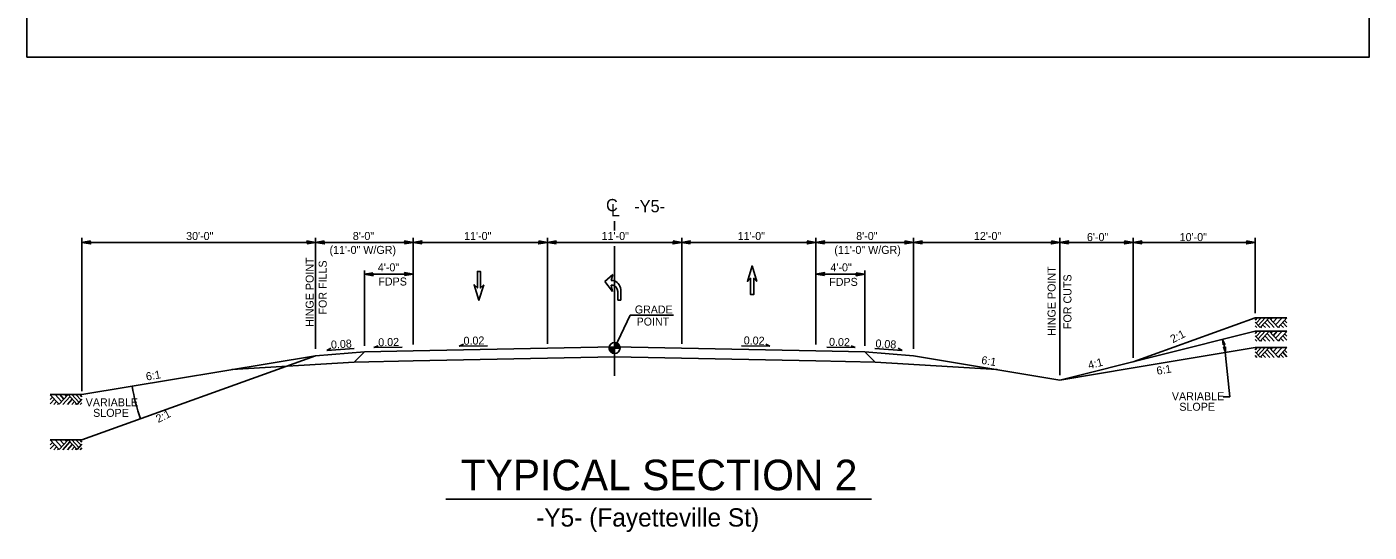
# Model space of a CAD drawing. Extents: x 1901718 to 1902220, y 193828 to 194187.
# Drawn here: x 1901718.5 to 1901828.5, y 194063.4 to 194104.8 of the extents above; entities that cross this region are included whole.
import ezdxf

# ---------------------------------------------------------------- set-up
doc = ezdxf.new("R2010")
doc.units = 0
for name, color, linetype in [('Default', 7, 'Continuous'), ('MARK BIKE LEFT ARROW CELL', 7, 'Continuous'), ('Old_Level_1', 7, 'Continuous'), ('Old_Level_2', 7, 'Continuous'), ('Prop Dimension', 7, 'Continuous'), ('Prop Dimension Text', 7, 'Continuous'), ('Scratch_Level_0', 7, 'Continuous'), ('Typical Hinge Slope Interstate CELL', 7, 'Continuous'), ('Typical Pavement Slope CELL', 7, 'Continuous'), ('Typical Terminator CELL', 7, 'Continuous'), ('Typical Text Grade Point CELL', 7, 'Continuous')]:
    doc.layers.add(name, color=color, linetype=linetype)

# ---------------------------------------------------------------- blocks, each defined once
blk = doc.blocks.new('TERMINATOR')
at = {"layer": 'Typical Terminator CELL'}
blk.add_lwpolyline([(-0.469, 0.081), (0, 0), (-0.471, -0.083), (-0.411, 0)], close=True, dxfattribs=at)

msp = doc.modelspace()

# ---------------------------------------------------------------- linework, layer by layer
at = {"layer": 'Default'}
msp.add_arc((1901742.14, 194077.84), 15.24, 189.4623, 199.8119, dxfattribs=at)
at = {"layer": 'MARK BIKE LEFT ARROW CELL'}
for p, q in [((1901766.5, 194084.5), (1901765.85, 194083.92)), ((1901766.5, 194084.5), (1901765.85, 194083.92)), ((1901766.35, 194083.99), (1901766.5, 194084.5)), ((1901766.35, 194083.99), (1901766.5, 194084.5)), ((1901765.85, 194083.92), (1901766.47, 194083.11)), ((1901765.85, 194083.92), (1901766.47, 194083.11)), ((1901766.52, 194083.99), (1901766.35, 194083.99)), ((1901766.52, 194083.99), (1901766.35, 194083.99)), ((1901766.47, 194083.11), (1901766.35, 194083.63)), ((1901766.35, 194083.63), (1901766.5, 194083.63)), ((1901766.47, 194083.11), (1901766.35, 194083.63)), ((1901766.35, 194083.63), (1901766.5, 194083.63)), ((1901766.92, 194083.11), (1901766.92, 194082.4)), ((1901766.92, 194083.11), (1901766.92, 194082.4)), ((1901767.15, 194082.4), (1901767.15, 194083.26)), ((1901767.15, 194082.4), (1901767.15, 194083.26)), ((1901766.92, 194082.4), (1901767.15, 194082.4)), ((1901766.92, 194082.4), (1901767.15, 194082.4))]:
    msp.add_line(p, q, dxfattribs=at)
for centre, major_axis, ratio in [((1901766.57, 194083.17), (-0.204, 0.44), 0.652763), ((1901766.57, 194083.17), (-0.204, 0.44), 0.652763), ((1901766.59, 194083.33), (-0.294, 0.632), 0.75825), ((1901766.59, 194083.33), (-0.294, 0.632), 0.75825)]:
    msp.add_ellipse(centre, major_axis=major_axis, ratio=ratio, start_param=4.277405, end_param=5.848201, dxfattribs=at)
at = {"layer": 'Old_Level_1'}
for p, q in [((1901766.64, 194088.1), (1901766.64, 194088.85)), ((1901766.64, 194076.18), (1901766.64, 194086.82)), ((1901819.31, 194080.94), (1901819.14, 194080.76)), ((1901819.63, 194080.94), (1901819.21, 194080.5)), ((1901819.96, 194080.94), (1901819.38, 194080.32)), ((1901820.28, 194080.94), (1901819.54, 194080.15)), ((1901820.7, 194080.14), (1901820.12, 194080.77)), ((1901821.01, 194080.16), (1901820.28, 194080.94)), ((1901820.55, 194080.94), (1901820.41, 194080.8)), ((1901820.95, 194080.94), (1901820.61, 194080.58)), ((1901821.35, 194080.94), (1901820.81, 194080.37)), ((1901821.74, 194080.93), (1901821.01, 194080.16)), ((1901821.74, 194080.53), (1901821.55, 194080.73)), ((1901819.54, 194080.15), (1901819.14, 194080.58)), ((1901819.27, 194080.14), (1901819.14, 194080.28)), ((1901819.31, 194079.84), (1901819.14, 194079.66)), ((1901819.63, 194079.84), (1901819.21, 194079.4)), ((1901819.96, 194079.84), (1901819.38, 194079.22)), ((1901820.28, 194079.84), (1901819.54, 194079.04)), ((1901819.67, 194080.14), (1901819.6, 194080.21)), ((1901819.97, 194080.14), (1901819.75, 194080.37)), ((1901820.33, 194080.14), (1901819.93, 194080.57)), ((1901820.7, 194079.04), (1901820.12, 194079.66)), ((1901821.01, 194079.05), (1901820.28, 194079.84)), ((1901820.55, 194079.84), (1901820.41, 194079.7)), ((1901820.95, 194079.84), (1901820.61, 194079.48)), ((1901821.35, 194079.84), (1901820.81, 194079.27)), ((1901821.74, 194079.83), (1901821.01, 194079.05)), ((1901821.14, 194080.14), (1901821.07, 194080.21)), ((1901821.45, 194080.14), (1901821.22, 194080.38)), ((1901821.74, 194080.2), (1901821.39, 194080.57)), ((1901821.74, 194079.43), (1901821.55, 194079.63)), ((1901746.92, 194078.5), (1901747.26, 194078.66)), ((1901749.24, 194078.54), (1901746.92, 194078.5)), ((1901766.64, 194078.58), (1901750.14, 194078.25)), ((1901753.91, 194078.62), (1901754.25, 194078.78)), ((1901756.23, 194078.66), (1901753.91, 194078.62)), ((1901766.64, 194078.47), (1901766.64, 194078.92)), ((1901766.64, 194078.58), (1901783.14, 194078.25)), ((1901777.04, 194078.66), (1901779.36, 194078.62)), ((1901779.36, 194078.62), (1901779.03, 194078.78)), ((1901784.04, 194078.54), (1901786.35, 194078.5)), ((1901786.35, 194078.5), (1901786.02, 194078.66)), ((1901817.05, 194074.47), (1901816.61, 194078.64)), ((1901819.54, 194079.04), (1901819.14, 194079.48)), ((1901819.27, 194079.04), (1901819.14, 194079.18)), ((1901819.31, 194078.51), (1901819.14, 194078.32)), ((1901819.63, 194078.51), (1901819.21, 194078.06)), ((1901819.96, 194078.51), (1901819.38, 194077.88)), ((1901820.28, 194078.51), (1901819.54, 194077.71)), ((1901819.67, 194079.04), (1901819.6, 194079.11)), ((1901819.97, 194079.04), (1901819.75, 194079.27)), ((1901820.33, 194079.04), (1901819.93, 194079.46)), ((1901821.01, 194077.72), (1901820.28, 194078.51)), ((1901820.55, 194078.51), (1901820.41, 194078.36)), ((1901820.95, 194078.51), (1901820.61, 194078.15)), ((1901821.35, 194078.51), (1901820.81, 194077.93)), ((1901821.14, 194079.04), (1901821.07, 194079.11)), ((1901821.45, 194079.04), (1901821.22, 194079.28)), ((1901821.74, 194079.1), (1901821.39, 194079.46)), ((1901746.14, 194078.17), (1901742.14, 194077.84)), ((1901743.07, 194078.27), (1901743.4, 194078.45)), ((1901745.31, 194078.42), (1901743.07, 194078.27)), ((1901745.29, 194077.32), (1901746.14, 194078.17)), ((1901750.14, 194077.42), (1901745.29, 194077.32)), ((1901750.14, 194078.25), (1901746.14, 194078.17)), ((1901766.64, 194077.75), (1901750.14, 194077.42)), ((1901766.19, 194078.47), (1901766.64, 194078.47)), ((1901767.09, 194078.47), (1901766.64, 194078.47)), ((1901766.64, 194078.02), (1901766.64, 194078.47)), ((1901766.64, 194078.47), (1901766.64, 194078.02)), ((1901766.64, 194077.75), (1901783.14, 194077.42)), ((1901783.14, 194078.25), (1901787.14, 194078.17)), ((1901783.14, 194077.42), (1901787.99, 194077.32)), ((1901787.99, 194077.32), (1901787.14, 194078.17)), ((1901787.14, 194078.17), (1901791.14, 194077.84)), ((1901787.97, 194078.42), (1901790.2, 194078.27)), ((1901790.2, 194078.27), (1901789.88, 194078.45)), ((1901791.14, 194077.84), (1901803.14, 194075.84)), ((1901819.54, 194077.71), (1901819.14, 194078.15)), ((1901819.27, 194077.7), (1901819.14, 194077.85)), ((1901819.67, 194077.7), (1901819.6, 194077.78)), ((1901819.97, 194077.7), (1901819.75, 194077.94)), ((1901820.33, 194077.7), (1901819.93, 194078.13)), ((1901820.7, 194077.7), (1901820.12, 194078.33)), ((1901821.74, 194078.5), (1901821.01, 194077.72)), ((1901821.14, 194077.7), (1901821.07, 194077.78)), ((1901821.45, 194077.7), (1901821.22, 194077.95)), ((1901821.74, 194077.76), (1901821.39, 194078.13)), ((1901821.74, 194078.1), (1901821.55, 194078.3)), ((1901745.29, 194077.32), (1901735.28, 194076.7)), ((1901787.99, 194077.32), (1901797.99, 194076.7)), ((1901720.39, 194074.64), (1901721.12, 194073.86)), ((1901720.39, 194074.24), (1901720.58, 194074.44)), ((1901720.39, 194073.91), (1901720.74, 194074.27)), ((1901720.79, 194074.65), (1901721.32, 194074.08)), ((1901721.12, 194073.86), (1901721.85, 194074.65)), ((1901721.18, 194074.65), (1901721.52, 194074.29)), ((1901721.43, 194073.84), (1901722.01, 194074.47)), ((1901721.59, 194074.65), (1901721.72, 194074.51)), ((1901721.8, 194073.84), (1901722.2, 194074.27)), ((1901721.85, 194074.65), (1901722.59, 194073.85)), ((1901722.17, 194074.65), (1901722.75, 194074.03)), ((1901722.5, 194074.65), (1901722.92, 194074.21)), ((1901722.59, 194073.85), (1901722.99, 194074.29)), ((1901722.82, 194074.65), (1901722.99, 194074.47)), ((1901817.05, 194074.47), (1901816.5, 194074.47)), ((1901720.68, 194073.84), (1901720.91, 194074.09)), ((1901720.99, 194073.84), (1901721.06, 194073.92)), ((1901722.16, 194073.84), (1901722.38, 194074.08)), ((1901722.46, 194073.84), (1901722.53, 194073.92)), ((1901722.86, 194073.84), (1901722.99, 194073.99)), ((1901720.39, 194070.94), (1901721.12, 194070.16)), ((1901720.79, 194070.94), (1901721.32, 194070.37)), ((1901721.12, 194070.16), (1901721.85, 194070.94)), ((1901721.18, 194070.94), (1901721.52, 194070.59)), ((1901721.59, 194070.94), (1901721.72, 194070.8)), ((1901721.85, 194070.94), (1901722.59, 194070.15)), ((1901722.17, 194070.94), (1901722.75, 194070.32)), ((1901722.5, 194070.94), (1901722.92, 194070.5)), ((1901722.82, 194070.94), (1901722.99, 194070.76)), ((1901720.39, 194070.54), (1901720.58, 194070.74)), ((1901720.39, 194070.2), (1901720.74, 194070.57)), ((1901720.68, 194070.14), (1901720.91, 194070.38)), ((1901720.99, 194070.14), (1901721.06, 194070.22)), ((1901721.43, 194070.14), (1901722.01, 194070.77)), ((1901721.8, 194070.14), (1901722.2, 194070.57)), ((1901722.16, 194070.14), (1901722.38, 194070.37)), ((1901722.46, 194070.14), (1901722.53, 194070.21)), ((1901722.59, 194070.15), (1901722.99, 194070.58)), ((1901722.86, 194070.14), (1901722.99, 194070.28)), ((1901752.81, 194066.09), (1901787.7, 194066.09))]:
    msp.add_line(p, q, dxfattribs=at)
for points in [[(1901821.74, 194080.94), (1901819.14, 194080.94)], [(1901821.74, 194079.84), (1901819.14, 194079.84)], [(1901766.64, 194078.92), (1901766.64, 194078.92), (1901766.64, 194078.47)], [(1901766.65, 194078.92), (1901766.65, 194078.47)], [(1901766.66, 194078.92), (1901766.66, 194078.47)], [(1901766.67, 194078.92), (1901766.67, 194078.47)], [(1901766.68, 194078.92), (1901766.68, 194078.47)], [(1901766.69, 194078.92), (1901766.69, 194078.47)], [(1901766.69, 194078.92), (1901766.69, 194078.47)], [(1901766.7, 194078.92), (1901766.7, 194078.47)], [(1901766.71, 194078.92), (1901766.71, 194078.47)], [(1901766.72, 194078.92), (1901766.72, 194078.47)], [(1901766.73, 194078.91), (1901766.73, 194078.47)], [(1901766.74, 194078.91), (1901766.74, 194078.47)], [(1901766.75, 194078.91), (1901766.75, 194078.47)], [(1901766.76, 194078.91), (1901766.76, 194078.47)], [(1901766.77, 194078.9), (1901766.77, 194078.47)], [(1901766.78, 194078.9), (1901766.78, 194078.47)], [(1901766.78, 194078.9), (1901766.78, 194078.47)], [(1901766.79, 194078.9), (1901766.79, 194078.47)], [(1901766.8, 194078.89), (1901766.8, 194078.47)], [(1901766.81, 194078.89), (1901766.81, 194078.47)], [(1901766.82, 194078.88), (1901766.82, 194078.47)], [(1901766.83, 194078.88), (1901766.83, 194078.47)], [(1901766.84, 194078.88), (1901766.84, 194078.47)], [(1901766.85, 194078.87), (1901766.85, 194078.47)], [(1901766.86, 194078.87), (1901766.86, 194078.47)], [(1901766.87, 194078.86), (1901766.87, 194078.47)], [(1901766.87, 194078.86), (1901766.87, 194078.47)], [(1901766.88, 194078.85), (1901766.88, 194078.47)], [(1901766.89, 194078.84), (1901766.89, 194078.47)], [(1901766.9, 194078.84), (1901766.9, 194078.47)], [(1901766.91, 194078.83), (1901766.91, 194078.47)], [(1901766.92, 194078.82), (1901766.92, 194078.47)], [(1901766.93, 194078.82), (1901766.93, 194078.47)], [(1901766.94, 194078.81), (1901766.94, 194078.47)], [(1901766.95, 194078.8), (1901766.95, 194078.47)], [(1901766.96, 194078.79), (1901766.96, 194078.47)], [(1901766.96, 194078.78), (1901766.96, 194078.47)], [(1901766.97, 194078.77), (1901766.97, 194078.47)], [(1901766.98, 194078.76), (1901766.98, 194078.47)], [(1901766.99, 194078.75), (1901766.99, 194078.47)], [(1901767, 194078.74), (1901767, 194078.47)], [(1901767.01, 194078.72), (1901767.01, 194078.47)], [(1901767.02, 194078.71), (1901767.02, 194078.47)], [(1901767.03, 194078.7), (1901767.03, 194078.47)], [(1901767.04, 194078.68), (1901767.04, 194078.47)], [(1901767.05, 194078.66), (1901767.05, 194078.47)], [(1901767.05, 194078.64), (1901767.05, 194078.47)], [(1901767.06, 194078.61), (1901767.06, 194078.47)], [(1901767.07, 194078.58), (1901767.07, 194078.47)], [(1901767.08, 194078.54), (1901767.08, 194078.47)], [(1901821.74, 194078.51), (1901819.14, 194078.51)], [(1901766.19, 194078.47), (1901766.19, 194078.42)], [(1901766.2, 194078.47), (1901766.2, 194078.37)], [(1901766.21, 194078.47), (1901766.21, 194078.34)], [(1901766.22, 194078.47), (1901766.22, 194078.31)], [(1901766.22, 194078.47), (1901766.22, 194078.29)], [(1901766.23, 194078.47), (1901766.23, 194078.27)], [(1901766.24, 194078.47), (1901766.24, 194078.26)], [(1901766.25, 194078.47), (1901766.25, 194078.24)], [(1901766.26, 194078.47), (1901766.26, 194078.23)], [(1901766.27, 194078.47), (1901766.27, 194078.21)], [(1901766.28, 194078.47), (1901766.28, 194078.2)], [(1901766.29, 194078.47), (1901766.29, 194078.19)], [(1901766.3, 194078.47), (1901766.3, 194078.18)], [(1901766.31, 194078.47), (1901766.31, 194078.17)], [(1901766.31, 194078.47), (1901766.31, 194078.16)], [(1901766.32, 194078.47), (1901766.32, 194078.15)], [(1901766.33, 194078.47), (1901766.33, 194078.14)], [(1901766.34, 194078.47), (1901766.34, 194078.13)], [(1901766.35, 194078.47), (1901766.35, 194078.13)], [(1901766.36, 194078.47), (1901766.36, 194078.12)], [(1901766.37, 194078.47), (1901766.37, 194078.11)], [(1901766.38, 194078.47), (1901766.38, 194078.11)], [(1901766.39, 194078.47), (1901766.39, 194078.1)], [(1901766.4, 194078.47), (1901766.4, 194078.09)], [(1901766.4, 194078.47), (1901766.4, 194078.09)], [(1901766.41, 194078.47), (1901766.41, 194078.08)], [(1901766.42, 194078.47), (1901766.42, 194078.08)], [(1901766.43, 194078.47), (1901766.43, 194078.07)], [(1901766.44, 194078.47), (1901766.44, 194078.07)], [(1901766.45, 194078.47), (1901766.45, 194078.06)], [(1901766.46, 194078.47), (1901766.46, 194078.06)], [(1901766.47, 194078.47), (1901766.47, 194078.06)], [(1901766.48, 194078.47), (1901766.48, 194078.05)], [(1901766.49, 194078.47), (1901766.49, 194078.05)], [(1901766.49, 194078.47), (1901766.49, 194078.05)], [(1901766.5, 194078.47), (1901766.5, 194078.04)], [(1901766.51, 194078.47), (1901766.51, 194078.04)], [(1901766.52, 194078.47), (1901766.52, 194078.04)], [(1901766.53, 194078.47), (1901766.53, 194078.04)], [(1901766.54, 194078.47), (1901766.54, 194078.03)], [(1901766.55, 194078.47), (1901766.55, 194078.03)], [(1901766.56, 194078.47), (1901766.56, 194078.03)], [(1901766.57, 194078.47), (1901766.57, 194078.03)], [(1901766.58, 194078.47), (1901766.58, 194078.03)], [(1901766.58, 194078.47), (1901766.58, 194078.03)], [(1901766.59, 194078.47), (1901766.59, 194078.03)], [(1901766.6, 194078.47), (1901766.6, 194078.02)], [(1901766.61, 194078.47), (1901766.61, 194078.02)], [(1901766.62, 194078.47), (1901766.62, 194078.02)], [(1901766.63, 194078.47), (1901766.63, 194078.02), (1901766.63, 194078.02)], [(1901720.39, 194074.65), (1901722.99, 194074.65)], [(1901720.39, 194070.94), (1901722.99, 194070.94)]]:
    msp.add_lwpolyline(points, dxfattribs=at)
for points in [[(1901816.51, 194078.72), (1901816.47, 194079.17), (1901816.66, 194078.76), (1901816.57, 194078.79)], [(1901816.7, 194078.56), (1901816.71, 194078.1), (1901816.55, 194078.53), (1901816.64, 194078.49)]]:
    msp.add_lwpolyline(points, close=True, dxfattribs=at)
msp.add_circle((1901766.64, 194078.47), 0.45, dxfattribs=at)
for centre, radius, start, end in [((1901766.64, 194078.47), 0.45, 359.9905, 89.9905), ((1901807.64, 194076.59), 9.2, 9.4623, 16.3025), ((1901766.64, 194078.47), 0.45, 179.9905, 269.9905)]:
    msp.add_arc(centre, radius, start, end, dxfattribs=at)
at = {"layer": 'Prop Dimension'}
for p, q in [((1901722.99, 194074.94), (1901722.99, 194087.49)), ((1901750.14, 194079.8), (1901750.14, 194087.49)), ((1901761.14, 194078.81), (1901761.14, 194087.49)), ((1901772.14, 194078.81), (1901772.14, 194087.49)), ((1901783.14, 194079.8), (1901783.14, 194087.49)), ((1901750.14, 194087.12), (1901761.14, 194087.12)), ((1901761.14, 194087.12), (1901772.14, 194087.12)), ((1901772.14, 194087.12), (1901783.14, 194087.12))]:
    msp.add_line(p, q, dxfattribs=at)
for points in [[(1901778.31, 194083.93), (1901778.04, 194084.18), (1901778.04, 194082.85), (1901777.79, 194082.85), (1901777.79, 194084.18), (1901777.52, 194083.93), (1901777.91, 194085.2)], [(1901778.31, 194083.93), (1901778.04, 194084.18), (1901778.04, 194082.85), (1901777.79, 194082.85), (1901777.79, 194084.18), (1901777.52, 194083.93), (1901777.91, 194085.2)], [(1901755.92, 194083.65), (1901755.65, 194083.4), (1901755.65, 194084.74), (1901755.4, 194084.74), (1901755.4, 194083.4), (1901755.13, 194083.65), (1901755.53, 194082.38)], [(1901755.92, 194083.65), (1901755.65, 194083.4), (1901755.65, 194084.74), (1901755.4, 194084.74), (1901755.4, 194083.4), (1901755.13, 194083.65), (1901755.53, 194082.38)]]:
    msp.add_lwpolyline(points, close=True, dxfattribs=at)
at = {"layer": 'Prop Dimension Text'}
for p, q in [((1901742.14, 194078.64), (1901742.14, 194087.49)), ((1901742.14, 194078.4), (1901742.14, 194087.49)), ((1901750.14, 194078.75), (1901750.14, 194087.49)), ((1901783.14, 194078.75), (1901783.14, 194087.49)), ((1901791.14, 194078.4), (1901791.14, 194087.49)), ((1901803.14, 194076.25), (1901803.14, 194087.49)), ((1901809.14, 194077.66), (1901809.14, 194087.49)), ((1901819.14, 194081.33), (1901819.14, 194087.49)), ((1901722.99, 194087.12), (1901742.14, 194087.12)), ((1901742.14, 194087.12), (1901750.14, 194087.12)), ((1901791.14, 194087.12), (1901783.14, 194087.12)), ((1901803.14, 194087.12), (1901791.14, 194087.12)), ((1901809.14, 194087.12), (1901803.14, 194087.12)), ((1901819.14, 194087.12), (1901809.14, 194087.12)), ((1901746.14, 194078.66), (1901746.14, 194084.83)), ((1901750.14, 194084.52), (1901746.14, 194084.52)), ((1901783.14, 194084.52), (1901787.14, 194084.52)), ((1901787.14, 194078.66), (1901787.14, 194084.83))]:
    msp.add_line(p, q, dxfattribs=at)
at = {"layer": 'Scratch_Level_0'}
msp.add_lwpolyline([(1901718.48, 194187.31), (1901828.48, 194187.31), (1901828.48, 194102.31), (1901718.48, 194102.31)], close=True, dxfattribs=at)
at = {"layer": 'Typical Hinge Slope Interstate CELL'}
for p, q in [((1901803.14, 194075.84), (1901819.14, 194079.84)), ((1901809.14, 194076.84), (1901819.14, 194078.51)), ((1901742.14, 194077.84), (1901722.99, 194074.65)), ((1901809.14, 194076.84), (1901803.14, 194075.84))]:
    msp.add_line(p, q, dxfattribs=at)
at = {"layer": 'Typical Pavement Slope CELL'}
for p, q in [((1901809.14, 194077.34), (1901819.14, 194080.94)), ((1901722.99, 194070.94), (1901742.14, 194077.84))]:
    msp.add_line(p, q, dxfattribs=at)
at = {"layer": 'Typical Text Grade Point CELL'}
for p, q in [((1901766.64, 194078.47), (1901767.93, 194081.15)), ((1901767.93, 194081.15), (1901771.47, 194081.15))]:
    msp.add_line(p, q, dxfattribs=at)

# ---------------------------------------------------------------- block references
at = {"layer": 'Prop Dimension', "xscale": 1.5, "rotation": 180}
for p, yscale in [((1901722.99, 194087.12), -1.5), ((1901742.14, 194087.12), -1.5), ((1901750.14, 194087.12), 1.5), ((1901761.14, 194087.12), 1.5), ((1901772.14, 194087.12), 1.5), ((1901783.14, 194087.12), 1.5), ((1901791.14, 194087.12), 1.5), ((1901803.14, 194087.12), 1.5), ((1901809.14, 194087.12), 1.5), ((1901746.14, 194084.52), -1.5), ((1901783.14, 194084.52), 1.5)]:
    msp.add_blockref('TERMINATOR', p, dxfattribs=dict(at, yscale=yscale))
at = {"layer": 'Prop Dimension', "xscale": 1.5}
for p, yscale in [((1901742.14, 194087.12), -1.5), ((1901750.14, 194087.12), -1.5), ((1901761.14, 194087.12), 1.5), ((1901772.14, 194087.12), 1.5), ((1901783.14, 194087.12), 1.5), ((1901791.14, 194087.12), 1.5), ((1901803.14, 194087.12), 1.5), ((1901809.14, 194087.12), 1.5), ((1901819.14, 194087.12), 1.5), ((1901750.14, 194084.52), -1.5), ((1901787.14, 194084.52), 1.5)]:
    msp.add_blockref('TERMINATOR', p, dxfattribs=dict(at, yscale=yscale))

# ---------------------------------------------------------------- texts
at = {"layer": 'Old_Level_1'}
for s, rotation, p in [('2:1', 26.565, (1901812.38, 194078.86)), ('VARIABLE', 0, (1901723.3, 194073.69)), ('VARIABLE', 360, (1901812.31, 194074.19)), ('SLOPE', 0, (1901723.91, 194072.83)), ('2:1', 26.565, (1901729.25, 194072.32)), ('SLOPE', 360, (1901812.92, 194073.33))]:
    msp.add_text(s, height=0.656, rotation=rotation, dxfattribs=at).set_placement(p)
msp.add_text('TYPICAL SECTION 2', height=2.5, dxfattribs=at).set_placement((1901754.03, 194066.82))
at = {"layer": 'Old_Level_2'}
msp.add_text('C', height=1, dxfattribs=at).set_placement((1901765.94, 194089.68))
for s, height, rotation, p in [('L', 1, 359.9469, (1901766.34, 194089.27)), ('-Y5-', 1, 359.9469, (1901768.25, 194089.59)), ('0.08', 0.656, 3.7166, (1901743.42, 194078.41)), ('0.02', 0.656, 1.1916, (1901747.28, 194078.61)), ('0.02', 0.656, 1.1916, (1901754.27, 194078.73)), ('0.02', 0.656, 358.8084, (1901777.22, 194078.77)), ('0.02', 0.656, 358.8084, (1901784.21, 194078.65)), ('0.08', 0.656, 356.2834, (1901788, 194078.53))]:
    msp.add_text(s, height=height, rotation=rotation, dxfattribs=at).set_placement(p)
at = {"layer": 'Prop Dimension'}
for s, p in [('11\'-0" ', (1901754.31, 194087.32)), ('11\'-0" ', (1901765.58, 194087.32)), ('11\'-0" ', (1901776.73, 194087.32)), ('12\'-0" ', (1901796.09, 194087.32))]:
    msp.add_text(s, height=0.656, dxfattribs=at).set_placement(p)
at = {"layer": 'Prop Dimension Text'}
for s, p in [('30\'-0"', (1901731.53, 194087.32)), ('4\'-0"', (1901784.33, 194084.75))]:
    msp.add_text(s, height=0.656, rotation=360, dxfattribs=at).set_placement(p)
for s, height, p in [('8\'-0"', 0.656, (1901745.19, 194087.32)), ('8\'-0"', 0.656, (1901786.44, 194087.32)), ('6\'-0"', 0.656, (1901805.35, 194087.23)), ('10\'-0"', 0.656, (1901812.95, 194087.23)), ('(11\'-0" W/GR)', 0.656, (1901743.28, 194086.18)), ('(11\'-0" W/GR)', 0.656, (1901784.65, 194086.18)), ('4\'-0"', 0.656, (1901747.24, 194084.75)), ('FDPS', 0.656, (1901747.28, 194083.59)), ('FDPS', 0.656, (1901784.23, 194083.56)), ('-Y5- (Fayetteville St) ', 1.5, (1901760.21, 194063.84))]:
    msp.add_text(s, height=height, dxfattribs=at).set_placement(p)
at = {"layer": 'Typical Hinge Slope Interstate CELL'}
for s, rotation, p in [('HINGE POINT', 90, (1901741.98, 194080.19)), ('FOR FILLS', 90, (1901743.05, 194081.21)), ('HINGE POINT', 90, (1901802.78, 194079.46)), ('FOR CUTS', 90, (1901804.08, 194080.02)), ('6:1', 350.5377, (1901796.66, 194077.18)), ('4:1', 14.4716, (1901805.53, 194076.73)), ('6:1', 9.4623, (1901728.29, 194075.8)), ('6:1', 9.4623, (1901811.11, 194076.27))]:
    msp.add_text(s, height=0.656, rotation=rotation, dxfattribs=at).set_placement(p)
at = {"layer": 'Typical Text Grade Point CELL'}
for s, p in [('GRADE', (1901768.3, 194081.3)), ('POINT', (1901768.45, 194080.31))]:
    msp.add_text(s, height=0.652, dxfattribs=at).set_placement(p)

doc.saveas('drawing.dxf')
